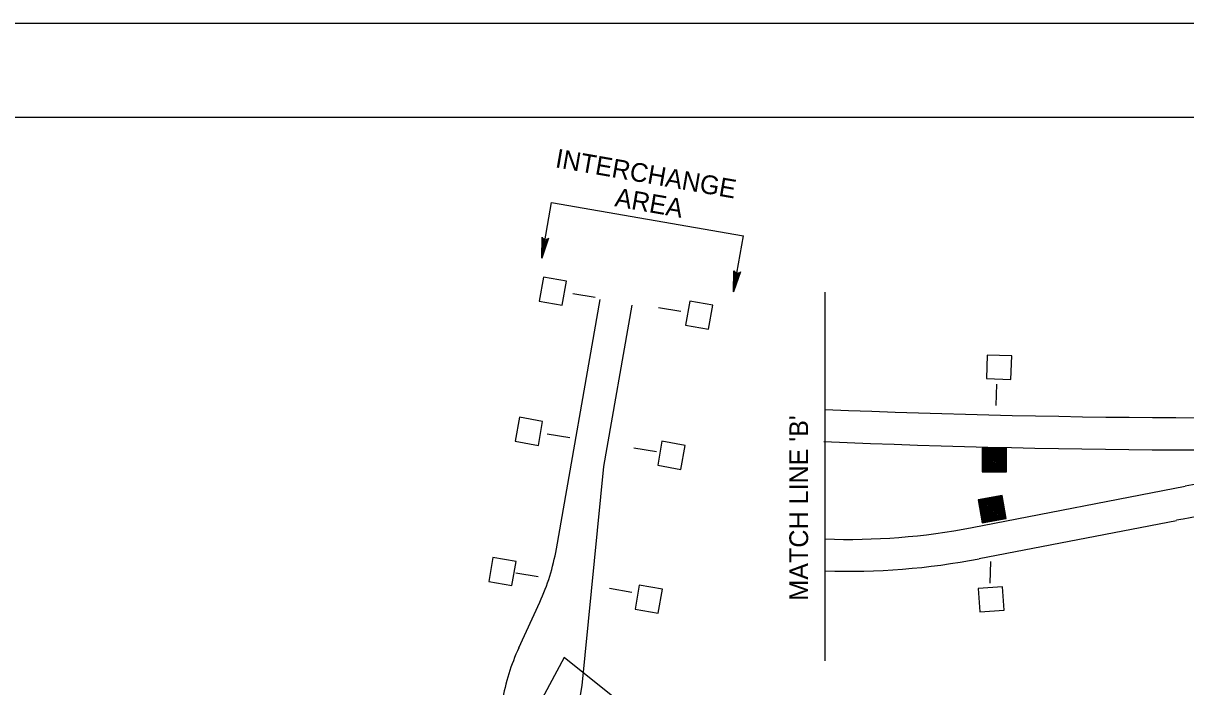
# Model space of a CAD drawing. Extents: x 640253 to 641999, y 298458 to 299646.
# Drawn here: x 641521.2 to 641707.1, y 299539.6 to 299645.6 of the extents above; entities that cross this region are included whole.
import ezdxf

# ---------------------------------------------------------------- set-up
doc = ezdxf.new("R2010")
doc.units = 0
for name, color, linetype in [('1', 7, 'Continuous'), ('2', 7, 'Continuous'), ('PLT-BNDY', 7, 'Continuous')]:
    doc.layers.add(name, color=color, linetype=linetype)

msp = doc.modelspace()

# ---------------------------------------------------------------- linework, layer by layer
at = {"layer": '1'}
msp.add_line((641134.31, 299630.63), (641920.31, 299630.63), dxfattribs=at)
at = {"layer": '2'}
for p, q in [((641604.1, 299608.07), (641605.66, 299616.99)), ((641605.66, 299616.99), (641636.34, 299611.63)), ((641634.77, 299602.71), (641636.34, 299611.63)), ((641609.07, 299602.45), (641612.66, 299601.86)), ((641649.42, 299543.72), (641649.42, 299602.62)), ((641606.45, 299561.61), (641613.42, 299601.46)), ((641614.05, 299574.76), (641618.56, 299600.56)), ((641622.76, 299600.19), (641626.35, 299599.6)), ((641676.79, 299584.52), (641676.87, 299587.96)), ((641604.99, 299580.02), (641608.58, 299579.43)), ((641618.84, 299577.75), (641622.43, 299577.16)), ((641610.58, 299539.79), (641614.05, 299574.76)), ((641672.93, 299565.02), (641707.01, 299571.63)), ((641674.04, 299560.09), (641705.59, 299566.17)), ((641675.83, 299556.13), (641675.91, 299559.57)), ((641599.94, 299557.77), (641603.53, 299557.18)), ((641614.92, 299555.31), (641618.51, 299554.71)), ((641600.44, 299545.81), (641603.79, 299553.1)), ((641591, 299427.89), (641610.58, 299539.79)), ((641610.58, 299539.79), (641610.58, 299539.79))]:
    msp.add_line(p, q, dxfattribs=at)
for points in [[(641605.04, 299611.11), (641604.8, 299611.04), (641604.1, 299608.07), (641605.04, 299611.11), (641605.2, 299611.25), (641604.1, 299608.07), (641604.49, 299611.09), (641604.28, 299611.23), (641604.1, 299608.07), (641604.15, 299611.42), (641604.28, 299611.23)], [(641635.71, 299605.75), (641635.47, 299605.67), (641634.77, 299602.71), (641635.71, 299605.75), (641635.87, 299605.88), (641634.77, 299602.71), (641635.15, 299605.73), (641634.95, 299605.87), (641634.77, 299602.71), (641634.83, 299606.06), (641634.95, 299605.87)], [(641674.52, 299573.95), (641678.42, 299573.95), (641678.42, 299577.7), (641674.52, 299577.7), (641674.52, 299573.95), (641678.36, 299577.62), (641674.59, 299577.62), (641674.59, 299574), (641678.36, 299574), (641678.36, 299577.56), (641674.66, 299577.56), (641674.66, 299574.07), (641678.28, 299574.07), (641678.27, 299577.47), (641674.73, 299577.47), (641674.73, 299574.13), (641678.21, 299574.13), (641678.21, 299577.41), (641674.8, 299577.41), (641674.8, 299574.19), (641678.13, 299574.19), (641678.12, 299577.34), (641674.87, 299577.34), (641674.86, 299574.25), (641678.07, 299574.26), (641678.04, 299577.27), (641674.94, 299577.27), (641674.93, 299574.31), (641678, 299574.33), (641677.98, 299577.2), (641675.01, 299577.2), (641674.98, 299574.39), (641677.91, 299574.41), (641677.91, 299577.11), (641675.09, 299577.12), (641675.06, 299574.44), (641677.81, 299574.49), (641677.82, 299577.05), (641675.17, 299577.05), (641675.13, 299574.51), (641677.73, 299574.55), (641677.73, 299576.99), (641675.25, 299576.97), (641675.21, 299574.55), (641677.64, 299574.61), (641677.64, 299576.92), (641675.34, 299576.89), (641675.29, 299575.79), (641675.29, 299574.61), (641677.57, 299574.69), (641677.54, 299576.82), (641675.42, 299576.78), (641675.38, 299574.69), (641677.48, 299574.76), (641677.45, 299576.74), (641675.52, 299576.68), (641675.48, 299574.78), (641677.35, 299574.83), (641677.33, 299576.61), (641675.66, 299576.57), (641675.6, 299574.91), (641677.21, 299574.94), (641677.19, 299576.51), (641675.81, 299576.45), (641675.74, 299575.02), (641675.74, 299575.02), (641677.06, 299575.07), (641677.05, 299576.36), (641675.95, 299576.32), (641675.88, 299575.15), (641676.91, 299575.21), (641676.92, 299576.2), (641676.09, 299576.19), (641676.05, 299575.31), (641676.75, 299575.34), (641676.72, 299576.08), (641676.25, 299576.05), (641676.23, 299575.44), (641676.57, 299575.47), (641676.57, 299575.92), (641676.43, 299575.95), (641676.41, 299575.59)], [(641674.53, 299565.77), (641678.37, 299566.45), (641677.71, 299570.14), (641673.88, 299569.46), (641674.53, 299565.77), (641677.67, 299570.06), (641673.95, 299569.41), (641674.58, 299565.84), (641678.29, 299566.49), (641677.68, 299569.99), (641674.04, 299569.35), (641674.64, 299565.91), (641678.21, 299566.54), (641677.61, 299569.89), (641674.12, 299569.27), (641674.7, 299565.98), (641678.13, 299566.59), (641677.56, 299569.82), (641674.2, 299569.23), (641674.76, 299566.05), (641678.04, 299566.64), (641677.48, 299569.74), (641674.28, 299569.18), (641674.81, 299566.12), (641677.96, 299566.7), (641677.42, 299569.65), (641674.36, 299569.11), (641674.86, 299566.2), (641677.88, 299566.75), (641677.37, 299569.57), (641674.44, 299569.06), (641674.91, 299566.29), (641677.78, 299566.81), (641677.32, 299569.47), (641674.54, 299569), (641674.97, 299566.35), (641677.67, 299566.87), (641677.24, 299569.4), (641674.63, 299568.94), (641675.03, 299566.43), (641677.59, 299566.92), (641677.16, 299569.33), (641674.72, 299568.88), (641675.1, 299566.48), (641677.49, 299566.97), (641677.08, 299569.24), (641674.82, 299568.8), (641674.96, 299567.71), (641675.17, 299566.56), (641677.4, 299567.03), (641677, 299569.12), (641674.92, 299568.72), (641675.24, 299566.65), (641677.3, 299567.09), (641676.93, 299569.03), (641675.04, 299568.64), (641675.33, 299566.76), (641677.17, 299567.13), (641676.84, 299568.88), (641675.19, 299568.55), (641675.42, 299566.9), (641677, 299567.21), (641676.71, 299568.75), (641675.36, 299568.46), (641675.54, 299567.04), (641675.55, 299567.04), (641676.83, 299567.32), (641676.6, 299568.59), (641675.52, 299568.36), (641675.66, 299567.19), (641676.65, 299567.43), (641676.49, 299568.41), (641675.68, 299568.24), (641675.8, 299567.37), (641676.48, 299567.52), (641676.32, 299568.25), (641675.87, 299568.14), (641675.95, 299567.54), (641676.29, 299567.63), (641676.21, 299568.07), (641676.06, 299568.07), (641676.1, 299567.72)], [(641635.54, 299521.92), (641607.68, 299544.27), (641603.36, 299536.2)]]:
    msp.add_lwpolyline(points, dxfattribs=at)
for points in [[(641607.39, 299600.56), (641608.06, 299604.4), (641604.37, 299605.05), (641603.7, 299601.21)], [(641630.78, 299596.73), (641631.45, 299600.57), (641627.76, 299601.21), (641627.09, 299597.37)], [(641675.22, 299588.85), (641679.12, 299588.71), (641679.25, 299592.46), (641675.35, 299592.59)], [(641603.56, 299578.16), (641604.23, 299582), (641600.54, 299582.65), (641599.87, 299578.81)], [(641626.35, 299574.32), (641627.02, 299578.16), (641623.33, 299578.81), (641622.65, 299574.97)], [(641599.32, 299555.76), (641599.99, 299559.6), (641596.3, 299560.24), (641595.63, 299556.4)], [(641622.71, 299551.32), (641623.39, 299555.16), (641619.69, 299555.8), (641619.02, 299551.96)], [(641674.17, 299551.55), (641678.05, 299551.81), (641677.79, 299555.55), (641673.9, 299555.28)]]:
    msp.add_lwpolyline(points, close=True, dxfattribs=at)
for centre, radius, start, end in [((641713.53, 301122.08), 1539.51, 267.61256, 276.52429), ((641713.53, 301122.08), 1544.66, 267.61256, 276.52429), ((641747.52, 299361.36), 214.14, 91.0236, 100.9066), ((641745, 299361.65), 208.29, 91.0236, 100.9066), ((641653.13, 299667.27), 104.14, 267.9574, 280.9617), ((641572.25, 299567.59), 34.71, 335.3192, 350.0612), ((641653.23, 299667.41), 109.37, 268.0001, 280.9651), ((641631.97, 299531.3), 34.71, 155.2901, 170.0975)]:
    msp.add_arc(centre, radius, start, end, dxfattribs=at)
at = {"layer": 'PLT-BNDY'}
msp.add_lwpolyline([(641094.31, 299645.63), (641935.31, 299645.63), (641935.31, 299051.63), (641094.31, 299051.63)], close=True, dxfattribs=at)

# ---------------------------------------------------------------- texts
at = {"layer": '2'}
for s, rotation, p in [('INTERCHANGE', 350.0808, (641606.14, 299622.63)), ('AREA', 350.0808, (641615.65, 299616.4)), ("MATCH LINE 'B'", 90, (641646.7, 299553.34))]:
    msp.add_text(s, height=3, rotation=rotation, dxfattribs=at).set_placement(p)

doc.saveas('drawing.dxf')
